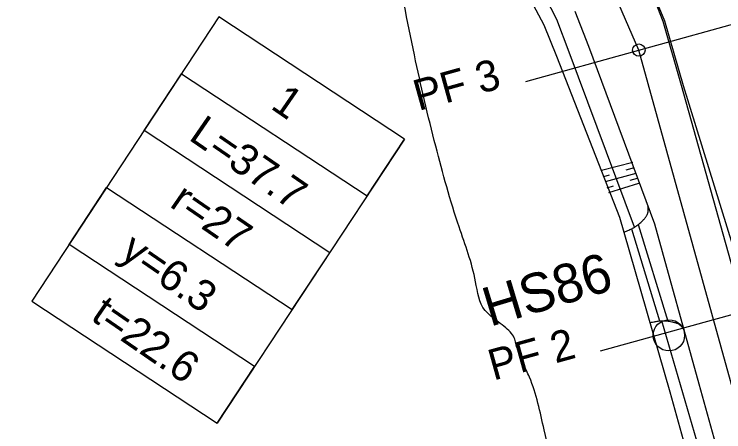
# Model space of a CAD drawing. Extents: x -478102 to -473059, y -1117705 to -1114104.
# Drawn here: x -476305.45 to -476260.09, y -1117088.23 to -1117061.5 of the extents above; entities that cross this region are included whole.
import ezdxf

# ---------------------------------------------------------------- set-up
doc = ezdxf.new("R2010")
doc.units = 0
for name, color, linetype in [('BodoveZnackySachtaKanalizacni', 7, 'Continuous'), ('cestn___p____kop', 7, 'Continuous'), ('cesty', 7, 'Continuous'), ('POLYGONY_SITUACE_PF', 7, 'Continuous'), ('POLYGONY_SITUACE_PF_POPISY', 7, 'Continuous'), ('POLYGONY_SITUACE_PO', 7, 'Continuous'), ('popis', 7, 'Continuous'), ('TABULKY', 7, 'Continuous'), ('TP_HS', 7, 'Continuous'), ('Vrstevnice_hlavni', 7, 'Continuous'), ('Vrstevnice_vedlejsi', 7, 'Continuous')]:
    doc.layers.add(name, color=color, linetype=linetype)

msp = doc.modelspace()

# ---------------------------------------------------------------- linework, layer by layer
at = {"layer": 'BodoveZnackySachtaKanalizacni'}
msp.add_circle((-476263.594, -1117082.052), 1, dxfattribs=at)
at = {"layer": 'cestn___p____kop'}
for p, q in [((-476265.9, -1117070.991), (-476267.895, -1117071.51)), ((-476265.814, -1117071.337), (-476266.354, -1117071.489)), ((-476267.765, -1117071.892), (-476267.384, -1117071.791)), ((-476265.713, -1117071.698), (-476267.664, -1117072.238)), ((-476265.626, -1117072.007), (-476266.087, -1117072.144)), ((-476267.549, -1117072.613), (-476267.146, -1117072.497)), ((-476265.533, -1117072.346), (-476267.456, -1117072.937))]:
    msp.add_line(p, q, dxfattribs=at)
at = {"layer": 'cesty'}
for p, q in [((-476270.762, -1117061.842), (-476271.976, -1117059.478)), ((-476268.718, -1117063.566), (-476269.578, -1117061.325)), ((-476269.962, -1117063.926), (-476270.762, -1117061.842)), ((-476264.504, -1117074.94), (-476268.718, -1117063.566)), ((-476265.802, -1117075.139), (-476269.962, -1117063.926)), ((-476262.821, -1117066.053), (-476259.518, -1117077.845)), ((-476262.685, -1117066.063), (-476259.083, -1117077.725)), ((-476261.667, -1117085.17), (-476264.504, -1117074.94)), ((-476258.59, -1117099.803), (-476264.043, -1117081.125)), ((-476261.133, -1117087.098), (-476261.667, -1117085.17)), ((-476260.599, -1117089.025), (-476261.133, -1117087.098))]:
    msp.add_line(p, q, dxfattribs=at)
for points in [[(-476266.732, -1117074.511), (-476270.768, -1117064.204), (-476271.566, -1117062.212), (-476272.761, -1117059.954), (-476273.936, -1117058.207), (-476275.415, -1117056.411), (-476278.317, -1117053.74), (-476280.366, -1117052.325), (-476282.34, -1117051.259), (-476283.992, -1117050.544), (-476285.595, -1117050.022), (-476288.167, -1117049.481), (-476290.873, -1117049.234), (-476293.603, -1117049.34), (-476293.603, -1117049.34), (-476299.076, -1117049.264)], [(-476265.008, -1117059.295), (-476263.985, -1117061.96), (-476262.821, -1117066.053)], [(-476264.959, -1117059.274), (-476263.868, -1117061.922), (-476262.685, -1117066.063)], [(-476266.45, -1117075.48), (-476266.732, -1117074.511)], [(-476263.521, -1117085.684), (-476266.45, -1117075.48)], [(-476262.981, -1117087.61), (-476263.521, -1117085.684)], [(-476262.442, -1117089.536), (-476262.981, -1117087.61)]]:
    msp.add_lwpolyline(points, dxfattribs=at)
at = {"layer": 'POLYGONY_SITUACE_PF'}
for points in [[(-476272.745, -1117065.801), (-476265.518, -1117063.797), (-476258.29, -1117061.793)], [(-476267.961, -1117083.054), (-476260.734, -1117081.05), (-476253.507, -1117079.047)]]:
    msp.add_lwpolyline(points, dxfattribs=at)
at = {"layer": 'POLYGONY_SITUACE_PO'}
msp.add_lwpolyline([(-476250.954, -1117100.054), (-476256.772, -1117095.342), (-476265.518, -1117063.797), (-476268.51, -1117056.912), (-476273.282, -1117051.116), (-476279.465, -1117046.859), (-476286.581, -1117044.469), (-476294.08, -1117044.131), (-476301.427, -1117045.065)], dxfattribs=at)
msp.add_circle((-476265.518, -1117063.797), 0.395, dxfattribs=at)
at = {"layer": 'TABULKY'}
msp.add_lwpolyline([(-476280.493, -1117069.495), (-476292.473, -1117087.683), (-476290.079, -1117084.049), (-476301.943, -1117076.234), (-476299.538, -1117072.584), (-476287.675, -1117080.398), (-476285.281, -1117076.764), (-476297.144, -1117068.949), (-476294.75, -1117065.315), (-476282.887, -1117073.129), (-476280.493, -1117069.495), (-476292.356, -1117061.68), (-476304.331, -1117079.86), (-476292.473, -1117087.683)], dxfattribs=at)
at = {"layer": 'TP_HS'}
for p, q in [((-476265.554, -1117074.971), (-476263.674, -1117081.139)), ((-476265.993, -1117075.246), (-476264.198, -1117081.134))]:
    msp.add_line(p, q, dxfattribs=at)
for points in [[(-476266.459, -1117075.447), (-476266.37, -1117075.412), (-476266.227, -1117075.352), (-476266.085, -1117075.289), (-476265.969, -1117075.234), (-476265.857, -1117075.172), (-476265.748, -1117075.106), (-476265.694, -1117075.07), (-476265.641, -1117075.034), (-476265.509, -1117074.935), (-476265.386, -1117074.827), (-476265.269, -1117074.711), (-476265.212, -1117074.65), (-476265.156, -1117074.588), (-476265.096, -1117074.517), (-476265.043, -1117074.443), (-476264.998, -1117074.365), (-476264.978, -1117074.323), (-476264.961, -1117074.279), (-476264.939, -1117074.212), (-476264.931, -1117074.177), (-476264.924, -1117074.142), (-476264.917, -1117074.074), (-476264.918, -1117074.005), (-476264.936, -1117073.778)], [(-476264.797, -1117081.237), (-476264.713, -1117081.218), (-476264.561, -1117081.188), (-476264.484, -1117081.174), (-476264.408, -1117081.161), (-476264.281, -1117081.142), (-476264.154, -1117081.131), (-476264.026, -1117081.125), (-476263.962, -1117081.124), (-476263.897, -1117081.124), (-476263.732, -1117081.133), (-476263.569, -1117081.154), (-476263.408, -1117081.185), (-476263.327, -1117081.203), (-476263.245, -1117081.224), (-476263.156, -1117081.249), (-476263.071, -1117081.281), (-476262.989, -1117081.321), (-476262.95, -1117081.344), (-476262.911, -1117081.371), (-476262.856, -1117081.415), (-476262.829, -1117081.439), (-476262.805, -1117081.464), (-476262.782, -1117081.49), (-476262.761, -1117081.517), (-476262.723, -1117081.575), (-476262.611, -1117081.773)]]:
    msp.add_spline(points, degree=3, dxfattribs=at)
at = {"layer": 'Vrstevnice_hlavni'}
msp.add_spline([(-476249.493, -1117108.392), (-476249.775, -1117107.699), (-476250.264, -1117106.97), (-476250.958, -1117106.207), (-476251.857, -1117105.408), (-476252.513, -1117105.14), (-476252.925, -1117105.402), (-476253.095, -1117106.195), (-476253.235, -1117107.1), (-476253.347, -1117108.118), (-476253.43, -1117109.248), (-476253.596, -1117109.985), (-476253.847, -1117110.328), (-476254.181, -1117110.278), (-476255.528, -1117110.336), (-476257.887, -1117110.502), (-476261.259, -1117110.776), (-476263.654, -1117110.928), (-476265.074, -1117110.957), (-476265.519, -1117110.863), (-476266.5, -1117108.002), (-476268.017, -1117102.375), (-476270.071, -1117093.98), (-476271.569, -1117088.098), (-476272.511, -1117084.73), (-476272.897, -1117083.874), (-476273.181, -1117083.184), (-476273.365, -1117082.66), (-476273.447, -1117082.301), (-476273.665, -1117081.937), (-476274.021, -1117081.569), (-476274.513, -1117081.196), (-476274.898, -1117080.887), (-476275.174, -1117080.644), (-476275.342, -1117080.466), (-476275.953, -1117078.624), (-476277.006, -1117075.118), (-476278.503, -1117069.948), (-476279.866, -1117064.113), (-476281.094, -1117057.612), (-476282.188, -1117050.447), (-476282.997, -1117045.306), (-476283.52, -1117042.188), (-476283.758, -1117041.094), (-476283.99, -1117040.218), (-476284.216, -1117039.561), (-476284.654, -1117038.684)], degree=3, dxfattribs=at)
at = {"layer": 'Vrstevnice_vedlejsi'}
for points in [[(-476361.641, -1116910.017), (-476360.991, -1116911.137), (-476360.552, -1116912.67), (-476360.323, -1116914.616), (-476360.306, -1116916.973), (-476360.308, -1116918.585), (-476360.329, -1116919.449), (-476360.369, -1116919.567), (-476360.386, -1116919.663), (-476360.38, -1116919.738), (-476360.35, -1116919.79), (-476360.486, -1116921.699), (-476360.787, -1116925.464), (-476361.254, -1116931.086), (-476361.67, -1116935.051), (-476362.037, -1116937.36), (-476362.353, -1116938.012), (-476362.549, -1116938.736), (-476362.623, -1116939.532), (-476362.576, -1116940.398), (-476362.264, -1116942.869), (-476361.686, -1116946.945), (-476360.843, -1116952.626), (-476360.093, -1116958.73), (-476359.435, -1116965.256), (-476358.871, -1116972.204), (-476358.36, -1116977.092), (-476357.904, -1116979.919), (-476357.501, -1116980.685), (-476356.57, -1116984.99), (-476355.11, -1116992.835), (-476353.122, -1117004.219), (-476351.571, -1117012.905), (-476350.455, -1117018.893), (-476349.776, -1117022.183), (-476349.504, -1117027.698), (-476349.639, -1117035.437), (-476350.182, -1117045.4), (-476350.307, -1117053.191), (-476350.012, -1117058.811), (-476349.298, -1117062.259), (-476350.091, -1117065.67), (-476352.39, -1117069.042), (-476356.195, -1117072.377), (-476359.92, -1117076.705), (-476363.566, -1117082.026), (-476367.131, -1117088.339), (-476371.33, -1117094.641), (-476376.164, -1117100.933), (-476381.631, -1117107.213), (-476386.474, -1117112.181), (-476390.692, -1117115.834), (-476394.286, -1117118.174), (-476397.491, -1117120.393), (-476400.306, -1117122.492), (-476402.732, -1117124.472), (-476402.928, -1117127.738), (-476400.894, -1117132.291), (-476396.631, -1117138.131), (-476389.647, -1117141.585), (-476379.944, -1117142.653), (-476367.521, -1117141.334), (-476355.525, -1117141.406), (-476343.957, -1117142.868), (-476332.816, -1117145.722), (-476324.482, -1117147.814), (-476318.952, -1117149.144), (-476316.229, -1117149.714), (-476310.745, -1117150.91), (-476302.502, -1117152.733), (-476291.498, -1117155.183), (-476284.107, -1117156.821), (-476280.33, -1117157.647), (-476280.165, -1117157.662), (-476279.816, -1117157.743), (-476279.284, -1117157.891), (-476278.569, -1117158.106), (-476278.072, -1117158.306), (-476277.796, -1117158.489), (-476277.739, -1117158.657), (-476277.684, -1117158.815), (-476277.629, -1117158.963), (-476277.576, -1117159.102), (-476277.523, -1117159.234), (-476277.472, -1117159.361), (-476277.423, -1117159.482), (-476277.379, -1117159.591), (-476277.34, -1117159.689), (-476277.307, -1117159.775), (-476277.275, -1117159.863), (-476277.243, -1117159.954), (-476277.212, -1117160.046), (-476277.173, -1117160.139), (-476277.129, -1117160.233), (-476277.078, -1117160.326), (-476277.04, -1117160.421), (-476277.015, -1117160.516)], [(-476223.981, -1117207.237), (-476224.285, -1117206.855), (-476224.501, -1117206.557), (-476224.628, -1117206.343), (-476224.668, -1117206.213), (-476224.801, -1117205.902), (-476225.026, -1117205.411), (-476225.345, -1117204.739), (-476225.578, -1117204.261), (-476225.727, -1117203.975), (-476225.791, -1117203.883), (-476225.875, -1117203.662), (-476225.98, -1117203.311), (-476226.105, -1117202.831), (-476226.229, -1117202.417), (-476226.352, -1117202.067), (-476226.475, -1117201.782), (-476226.572, -1117201.501), (-476226.643, -1117201.224), (-476226.689, -1117200.951), (-476227.057, -1117200.755), (-476227.747, -1117200.637), (-476228.759, -1117200.595), (-476229.446, -1117200.566), (-476229.808, -1117200.548), (-476229.845, -1117200.544), (-476229.875, -1117200.547), (-476229.898, -1117200.559), (-476229.914, -1117200.578), (-476229.923, -1117200.586), (-476229.927, -1117200.583), (-476229.925, -1117200.567), (-476229.926, -1117200.55), (-476229.93, -1117200.533), (-476229.937, -1117200.515), (-476230.309, -1117199.985), (-476231.045, -1117198.942), (-476232.146, -1117197.387), (-476233.138, -1117195.885), (-476234.022, -1117194.438), (-476234.797, -1117193.044), (-476236.35, -1117190.18), (-476238.683, -1117185.847), (-476241.794, -1117180.043), (-476244.171, -1117175.438), (-476245.814, -1117172.033), (-476246.723, -1117169.826), (-476247.372, -1117168.01), (-476247.761, -1117166.585), (-476247.891, -1117165.55), (-476248.161, -1117164.525), (-476248.57, -1117163.508), (-476249.119, -1117162.501), (-476249.598, -1117161.498), (-476250.007, -1117160.498), (-476250.346, -1117159.503), (-476250.69, -1117158.53), (-476251.038, -1117157.58), (-476251.39, -1117156.652), (-476251.803, -1117155.599), (-476252.277, -1117154.423), (-476252.812, -1117153.123), (-476253.36, -1117151.76), (-476253.922, -1117150.336), (-476254.497, -1117148.85), (-476255.085, -1117147.257), (-476255.684, -1117145.558), (-476256.294, -1117143.752), (-476259.267, -1117141.777), (-476264.603, -1117139.631), (-476272.302, -1117137.316), (-476278.025, -1117135.721), (-476281.773, -1117134.847), (-476283.545, -1117134.694), (-476286.438, -1117134.211), (-476290.451, -1117133.398), (-476295.585, -1117132.255), (-476301.704, -1117130.929), (-476308.808, -1117129.42), (-476316.898, -1117127.729), (-476324.767, -1117125.966), (-476332.416, -1117124.134), (-476339.844, -1117122.232), (-476344.627, -1117120.838), (-476346.763, -1117119.952), (-476346.254, -1117119.574), (-476345.231, -1117118.402), (-476343.693, -1117116.434), (-476341.642, -1117113.672), (-476338.379, -1117110.142), (-476333.906, -1117105.844), (-476328.223, -1117100.779), (-476323.405, -1117096.497), (-476319.453, -1117093.001), (-476316.366, -1117090.289), (-476314.122, -1117087.639), (-476312.721, -1117085.051)]]:
    msp.add_spline(points, degree=3, dxfattribs=at)

# ---------------------------------------------------------------- texts
for s, height, p in [('1', 1.976, (-476289.128, -1117067.495)), ('L=37.7', 1.9765, (-476294.363, -1117069.492)), ('r=27', 1.9765, (-476295.578, -1117073.775)), ('y=6.3', 1.9765, (-476298.783, -1117076.985)), ('t=22.6', 1.9765, (-476300.63, -1117081.012))]:
    msp.add_text(s, height=height, rotation=325.4518).set_placement(p)
at = {"layer": 'POLYGONY_SITUACE_PF_POPISY'}
for s, p in [('PF 3', (-476279.602, -1117067.702)), ('PF 2', (-476274.818, -1117084.955))]:
    msp.add_text(s, height=1.9765, rotation=15.4963, dxfattribs=at).set_placement(p)
at = {"layer": 'popis'}
msp.add_text('HS86', height=2.5, rotation=16.7821, dxfattribs=at).set_placement((-476275.034, -1117081.512))

doc.saveas('drawing.dxf')
